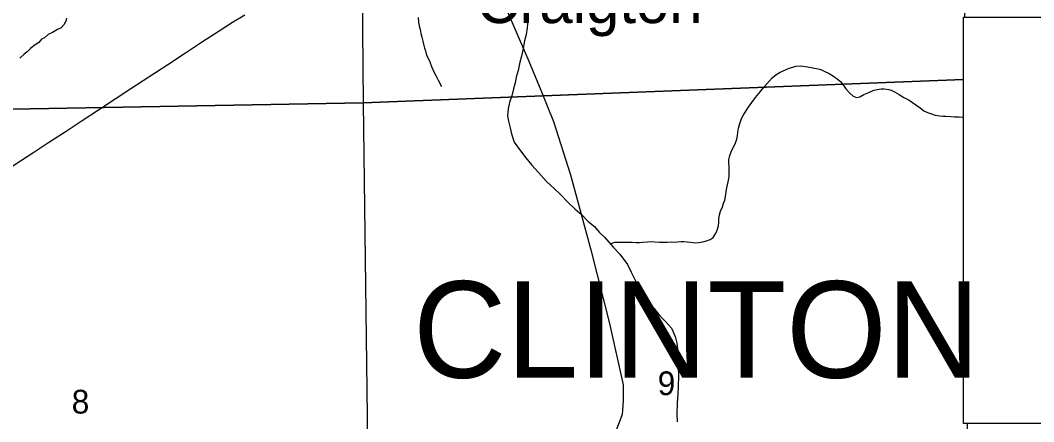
# Model space of a CAD drawing. Extents: x 0 to 34, y 0 to 22.
# Drawn here: x 4.826 to 6.615, y 16.821 to 17.529 of the extents above; entities that cross this region are included whole.
import ezdxf

# ---------------------------------------------------------------- set-up
doc = ezdxf.new("R2010")
doc.units = 0
for name, color, linetype in [('GM_X_Minor_River', 7, 'Continuous'), ('GM_X_Rail_Line', 7, 'Continuous'), ('GM_X_Section', 7, 'Continuous'), ('GM_X_Section_Text', 7, 'Continuous'), ('GM_X_State_Route', 7, 'Continuous'), ('GM_X_Township_Text', 7, 'Continuous'), ('GM_X_Unincorporated_Text', 7, 'Continuous'), ('SH_Text', 7, 'Continuous')]:
    doc.layers.add(name, color=color, linetype=linetype)

msp = doc.modelspace()

# ---------------------------------------------------------------- linework, layer by layer
at = {"layer": 'GM_X_Minor_River'}
for points in [[(4.9078, 17.5327), (4.9067, 17.5274), (4.9033, 17.521), (4.8983, 17.516), (4.8922, 17.5126), (4.8831, 17.5077), (4.8754, 17.5039), (4.8693, 17.4982), (4.864, 17.4959), (4.8594, 17.4902), (4.8507, 17.4845), (4.8442, 17.4792), (4.8385, 17.4735), (4.8335, 17.4693), (4.8259, 17.4624)], [(5.5287, 17.5343), (5.5291, 17.5252), (5.5303, 17.5191), (5.5318, 17.5126), (5.533, 17.5058), (5.5353, 17.4993), (5.5365, 17.4921), (5.538, 17.4867), (5.5399, 17.4799), (5.5415, 17.475), (5.543, 17.4677), (5.5468, 17.4609), (5.5491, 17.4559), (5.5522, 17.4476), (5.5564, 17.4381), (5.5603, 17.4305), (5.5637, 17.4236), (5.5699, 17.4122)], [(5.7223, 17.5298), (5.7208, 17.5158), (5.7189, 17.504), (5.716, 17.4926)], [(5.716, 17.4926), (5.713, 17.4763), (5.7108, 17.466), (5.7081, 17.4554), (5.7048, 17.4406), (5.7014, 17.4288), (5.6996, 17.4185), (5.697, 17.4083), (5.694, 17.3958), (5.6895, 17.384), (5.6872, 17.373), (5.6862, 17.3608), (5.6881, 17.3513), (5.6908, 17.3392), (5.6931, 17.3286), (5.6977, 17.3142), (5.7091, 17.2986), (5.7183, 17.2865), (5.7293, 17.2733), (5.7407, 17.2604), (5.7552, 17.2449), (5.7688, 17.2324), (5.7795, 17.2218), (5.792, 17.209), (5.805, 17.1961), (5.8171, 17.1859), (5.8285, 17.1738), (5.8396, 17.1651), (5.8479, 17.1552), (5.8574, 17.1466), (5.873, 17.128), (5.8844, 17.1163), (5.8981, 17.0981), (5.9043, 17.0845), (5.9127, 17.0682), (5.9188, 17.0553), (5.9264, 17.0447), (5.9348, 17.0318), (5.9443, 17.0208), (5.9553, 17.0076), (5.9648, 16.9977), (5.9755, 16.9856), (5.9823, 16.9709), (5.985, 16.9591), (5.9862, 16.9492), (5.9866, 16.936), (5.9875, 16.9174), (5.9879, 16.9014), (5.9872, 16.8828), (5.9865, 16.8692), (5.9858, 16.854), (5.9851, 16.8342), (5.9856, 16.8202)], [(5.8675, 17.1346), (5.8754, 17.1373), (5.8789, 17.1375), (5.906, 17.1374), (5.9132, 17.1367), (5.9193, 17.1367), (5.9247, 17.1374), (5.9331, 17.1382), (5.9396, 17.1386), (5.946, 17.1382), (5.9544, 17.1374), (5.9632, 17.1378), (5.9682, 17.1378), (5.9758, 17.1382), (5.9812, 17.1378), (5.9861, 17.1382), (5.9926, 17.1385), (5.9976, 17.1385), (6.0033, 17.1381), (6.009, 17.1374), (6.017, 17.1366), (6.0239, 17.137), (6.0308, 17.1381), (6.0372, 17.14), (6.0437, 17.1423), (6.0494, 17.1457), (6.0532, 17.1522), (6.0559, 17.1586), (6.0586, 17.1662), (6.0593, 17.172), (6.0593, 17.178), (6.0604, 17.186), (6.0619, 17.1925), (6.0654, 17.1997), (6.0672, 17.2066), (6.0695, 17.2115), (6.0714, 17.2214), (6.0722, 17.2267), (6.0733, 17.2332), (6.0744, 17.2389), (6.0755, 17.2442), (6.0771, 17.2526), (6.0774, 17.2609), (6.0774, 17.2708), (6.077, 17.2773), (6.0766, 17.2834), (6.0785, 17.2906), (6.0811, 17.297), (6.0834, 17.3024), (6.0861, 17.3077), (6.0884, 17.313), (6.091, 17.3195), (6.0918, 17.3252), (6.0929, 17.3316), (6.094, 17.3385), (6.0959, 17.3468), (6.0993, 17.3556), (6.102, 17.3609), (6.1081, 17.3708), (6.1115, 17.3757), (6.1176, 17.3841), (6.1237, 17.3928), (6.1298, 17.3997), (6.1339, 17.405), (6.1393, 17.4115), (6.1484, 17.4221), (6.1534, 17.4274), (6.1598, 17.4331), (6.1671, 17.4377), (6.177, 17.4419), (6.1835, 17.4445), (6.1896, 17.4464), (6.1953, 17.4479), (6.2025, 17.4487), (6.2159, 17.4468), (6.222, 17.4456), (6.2277, 17.4445), (6.2342, 17.4433), (6.2392, 17.4422), (6.2453, 17.4395), (6.2537, 17.435), (6.2617, 17.4308), (6.2682, 17.4258), (6.2744, 17.4205), (6.2797, 17.4133), (6.2835, 17.4083), (6.2904, 17.4007), (6.2962, 17.3954), (6.3019, 17.3927), (6.308, 17.3939), (6.3152, 17.398), (6.3236, 17.4018), (6.3328, 17.4056), (6.3385, 17.4068), (6.3454, 17.4079), (6.3507, 17.4083), (6.3591, 17.4071), (6.3645, 17.4052), (6.3694, 17.403), (6.3775, 17.3984), (6.3855, 17.3931)], [(6.3855, 17.3931), (6.395, 17.3881), (6.4011, 17.3843), (6.4065, 17.3797), (6.4145, 17.3748), (6.4206, 17.3691), (6.4271, 17.3664), (6.4325, 17.3645), (6.4409, 17.3619), (6.4493, 17.3607), (6.4546, 17.3599), (6.46, 17.3599), (6.4684, 17.3592), (6.4749, 17.3588), (6.4833, 17.3588), (6.4886, 17.3584), (6.4908, 17.3587)]]:
    msp.add_lwpolyline(points, dxfattribs=at)
at = {"layer": 'GM_X_Rail_Line'}
msp.add_lwpolyline([(5.3223, 18.8195), (5.4276, 18.6336), (5.4516, 18.5976), (5.462, 18.5676), (5.468, 18.5406), (5.4695, 18.5137), (5.4725, 18.1255), (5.4814, 18.07), (5.4919, 18.0086), (5.5024, 17.9621), (5.5234, 17.9081), (5.6581, 17.6099), (5.724, 17.457), (5.7449, 17.406), (5.7674, 17.3506), (5.7973, 17.2561), (5.8333, 17.1242), (5.8662, 16.9938), (5.8901, 16.8859), (5.8901, 16.8575), (5.8886, 16.8335), (5.7201, 16.39)], dxfattribs=at)
at = {"layer": 'GM_X_Section'}
for points in [[(4.4738, 18.4018), (5.4223, 18.414), (5.4312, 17.3835), (4.419, 17.3654), (4.4097, 18.4011)], [(6.4931, 17.5349), (6.4793, 18.4161), (5.4724, 18.4134), (5.4223, 18.414), (5.4312, 17.3835), (6.4908, 17.4246), (6.4908, 17.5349)], [(6.4908, 17.4246), (5.4312, 17.3835), (5.4444, 16.3706), (5.9855, 16.4024), (6.4997, 16.4098), (6.4977, 16.8178), (6.4908, 16.8178)], [(4.419, 17.3654), (5.4312, 17.3835), (5.4444, 16.3706), (5.3035, 16.3654), (4.4387, 16.3528)]]:
    msp.add_lwpolyline(points, close=True, dxfattribs=at)
at = {"layer": 'GM_X_State_Route'}
msp.add_lwpolyline([(4.7929, 17.259), (4.8267, 17.2809), (4.8501, 17.2962), (4.8735, 17.3115), (4.9073, 17.3336), (4.9358, 17.3523), (4.9644, 17.3711), (4.9955, 17.3914), (5.0215, 17.4085), (5.0865, 17.4511), (5.1177, 17.4715), (5.1462, 17.4903), (5.1775, 17.5105), (5.2011, 17.5256), (5.2227, 17.5389)], dxfattribs=at)
at = {"layer": 'SH_Text'}
msp.add_lwpolyline([(6.4908, 17.5349), (8.7107, 17.5349), (8.7107, 16.8178), (6.4908, 16.8178)], close=True, dxfattribs=at)

# ---------------------------------------------------------------- texts
at = {"layer": 'GM_X_Section_Text'}
for s, p in [('9', (5.9512, 16.8676)), ('8', (4.9171, 16.8351))]:
    msp.add_text(s, height=0.0419, rotation=0, dxfattribs=at).set_placement(p)
at = {"layer": 'GM_X_Township_Text'}
msp.add_text('CLINTON', height=0.17045, rotation=0, dxfattribs=at).set_placement((5.5196, 16.8982))
at = {"layer": 'GM_X_Unincorporated_Text'}
msp.add_text('Craigton', height=0.07898, rotation=0, dxfattribs=at).set_placement((5.6312, 17.5242))

doc.saveas('drawing.dxf')
